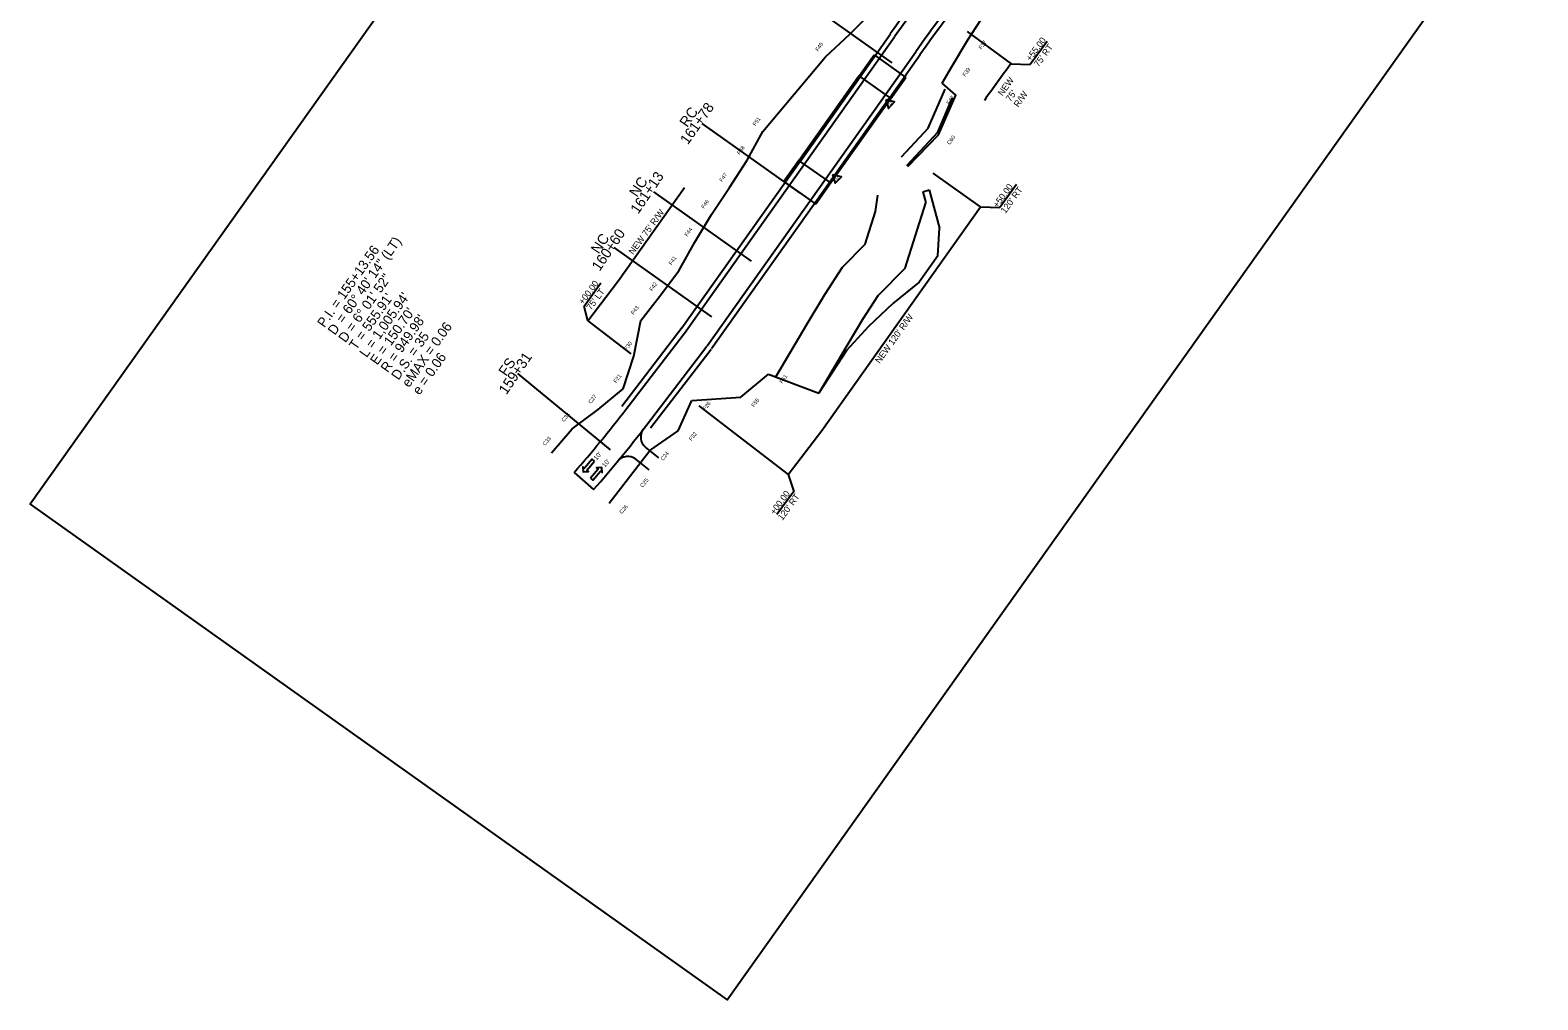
# Model space of a CAD drawing. Extents: x 1775013 to 1776177, y 1129170 to 1130432.
# Drawn here: x 1775013 to 1776177, y 1129170 to 1129918 of the extents above; entities that cross this region are included whole.
import ezdxf

# ---------------------------------------------------------------- set-up
doc = ezdxf.new("R2010")
doc.units = 0
for name, color, linetype in [('RD_EX_SU_Misc', 7, 'Continuous'), ('RD_HC_Data', 7, 'Continuous'), ('RD_HY_Misc', 7, 'Continuous'), ('RD_PD_Bridge', 7, 'Continuous'), ('RD_PD_CstnLmt', 7, 'Continuous'), ('RD_PD_CstnLmt_TX', 7, 'Continuous'), ('RD_PD_Final_TrvlWay', 7, 'Continuous'), ('RD_PD_Final_TX', 7, 'Continuous'), ('RD_PD_GR', 7, 'Continuous'), ('RD_PD_RW', 7, 'Continuous'), ('RD_PD_RW_TX', 7, 'Continuous'), ('RD_SHT_TX', 7, 'Continuous'), ('RD_Sketch2', 7, 'Continuous'), ('RD_Sketch8', 7, 'Continuous')]:
    doc.layers.add(name, color=color, linetype=linetype)

msp = doc.modelspace()

# ---------------------------------------------------------------- linework, layer by layer
at = {"layer": 'RD_EX_SU_Misc'}
for points in [[(1775673.9, 1129863.9), (1775675.9, 1129857.3), (1775680.7, 1129862.3)], [(1775632.8, 1129806.2), (1775634.8, 1129799.6), (1775639.6, 1129804.6)]]:
    msp.add_lwpolyline(points, close=True, dxfattribs=at)
at = {"layer": 'RD_HY_Misc'}
for p, q in [((1775706.6, 1129842.1), (1775719.7, 1129872.2)), ((1775714, 1129838.9), (1775725.5, 1129865.5)), ((1775706.6, 1129842.1), (1775685.8, 1129819.7)), ((1775714, 1129838.9), (1775689.8, 1129813)), ((1775666, 1129777.7), (1775667.8, 1129790.3)), ((1775688.8, 1129734.1), (1775704.8, 1129784.5)), ((1775702.5, 1129793.1), (1775704.8, 1129784.5)), ((1775658, 1129752.7), (1775666, 1129777.7)), ((1775658, 1129752.7), (1775640.3, 1129734.6)), ((1775640.3, 1129734.6), (1775626.6, 1129713.6)), ((1775688.8, 1129734.1), (1775667.7, 1129712.6)), ((1775626.6, 1129713.6), (1775613.8, 1129692.1)), ((1775667.7, 1129712.6), (1775655.9, 1129694.5)), ((1775613.8, 1129692.1), (1775588.8, 1129650.1)), ((1775656.7, 1129695.7), (1775643.8, 1129674.2)), ((1775643.8, 1129674.2), (1775622.1, 1129637.6))]:
    msp.add_line(p, q, dxfattribs=at)
at = {"layer": 'RD_PD_Bridge'}
for p, q in [((1775595.4, 1129800.8), (1775664.9, 1129898.7)), ((1775664.8, 1129898.7), (1775689.3, 1129881.3)), ((1775607.8, 1129816.5), (1775654.1, 1129881.8)), ((1775622, 1129786.8), (1775689.2, 1129881.4)), ((1775677.7, 1129865), (1775689.3, 1129881.3)), ((1775630.5, 1129800.4), (1775676.8, 1129865.7)), ((1775606.9, 1129817.2), (1775595.3, 1129800.9)), ((1775595.3, 1129800.9), (1775619.8, 1129783.5)), ((1775631.4, 1129799.8), (1775619.8, 1129783.5))]:
    msp.add_line(p, q, dxfattribs=at)
msp.add_lwpolyline([(1775606.9, 1129817.2), (1775653.2, 1129882.4), (1775677.7, 1129865), (1775631.4, 1129799.8)], close=True, dxfattribs=at)
at = {"layer": 'RD_PD_CstnLmt'}
for p, q in [((1775646.1, 1129914.5), (1775664, 1129932.5)), ((1775737.2, 1129910.3), (1775750.6, 1129930.9)), ((1775627.4, 1129897.1), (1775646.1, 1129914.5)), ((1775724.6, 1129889.2), (1775737.2, 1129910.3)), ((1775579, 1129839.4), (1775627.4, 1129897.1)), ((1775717.4, 1129876.7), (1775724.6, 1129889.2)), ((1775566.9, 1129817.4), (1775579, 1129839.4)), ((1775714.6, 1129836.9), (1775690.6, 1129812.2)), ((1775553.3, 1129796.3), (1775566.9, 1129817.4)), ((1775539.3, 1129775.6), (1775553.3, 1129796.3)), ((1775702.5, 1129793.1), (1775707.3, 1129794.4)), ((1775707.3, 1129794.4), (1775715.3, 1129765)), ((1775526.4, 1129754.1), (1775539.3, 1129775.6)), ((1775714.1, 1129743.5), (1775715.3, 1129765)), ((1775514.2, 1129732.1), (1775526.4, 1129754.1)), ((1775714.1, 1129743.5), (1775699.6, 1129723.2)), ((1775499.3, 1129712.1), (1775514.2, 1129732.1)), ((1775699.6, 1129723.2), (1775679.4, 1129706.8)), ((1775484.7, 1129693.7), (1775499.3, 1129712.1)), ((1775660.9, 1129689.3), (1775679.4, 1129706.8)), ((1775479.5, 1129666.1), (1775484.7, 1129693.7)), ((1775643.9, 1129670.7), (1775660.9, 1129689.3)), ((1775622.1, 1129637.6), (1775643.9, 1129670.7)), ((1775471.3, 1129640.9), (1775479.5, 1129666.1)), ((1775561.9, 1129634.5), (1775583.4, 1129652.4)), ((1775583.4, 1129652.4), (1775622.1, 1129637.6)), ((1775451.8, 1129624.9), (1775471.3, 1129640.9)), ((1775524.2, 1129631.9), (1775561.9, 1129634.5)), ((1775431.7, 1129610), (1775451.8, 1129624.9)), ((1775513.7, 1129608.5), (1775524.2, 1129631.9)), ((1775416, 1129591.6), (1775431.7, 1129610)), ((1775491.8, 1129593.3), (1775513.7, 1129608.5)), ((1775476.2, 1129573), (1775491.8, 1129593.3)), ((1775460.3, 1129552.8), (1775476.2, 1129573))]:
    msp.add_line(p, q, dxfattribs=at)
msp.add_lwpolyline([(1775714.6, 1129836.9), (1775727.9, 1129867.5), (1775717.4, 1129876.7)], dxfattribs=at)
at = {"layer": 'RD_PD_Final_TrvlWay'}
for p, q in [((1775519.7, 1129685.7), (1775680.7, 1129912.5)), ((1775536.1, 1129674.2), (1775697, 1129900.9)), ((1775473.2, 1129625.1), (1775520, 1129686)), ((1775489.1, 1129612.9), (1775535.8, 1129673.9)), ((1775491.2, 1129578.5), (1775480.9, 1129586.6)), ((1775498.7, 1129587.8), (1775488.5, 1129595.9)), ((1775433.3, 1129576.5), (1775448.3, 1129563.3))]:
    msp.add_line(p, q, dxfattribs=at)
for centre, radius, start, end in [((1777187.3, 1128843), 1847.7, 140.5283, 144.6285), ((1777187.3, 1128843), 1827.7, 140.5283, 144.6285), ((1774727.2, 1130196.9), 940, 318.6957, 322.5307), ((1774727.2, 1130196.9), 960, 318.6957, 322.5307), ((1775494.7, 1129603.8), 10, 142.302, 231.7113), ((1775474.7, 1129578.8), 10, 51.7113, 140.4117)]:
    msp.add_arc(centre, radius, start, end, dxfattribs=at)
at = {"layer": 'RD_PD_Final_TX'}
for points in [[(1775449.1, 1129585.2), (1775447.3, 1129586.8), (1775441.3, 1129579.8), (1775440.1, 1129580.9), (1775440.4, 1129576.9), (1775444.4, 1129577.2), (1775443.1, 1129578.3)], [(1775445.9, 1129572.1), (1775447.7, 1129570.6), (1775453.8, 1129577.5), (1775455, 1129576.4), (1775454.7, 1129580.4), (1775450.7, 1129580.1), (1775451.9, 1129579.1)]]:
    msp.add_lwpolyline(points, close=True, dxfattribs=at)
at = {"layer": 'RD_PD_GR'}
for p, q in [((1775654, 1129881.8), (1775677.5, 1129914.8)), ((1775700.3, 1129898.6), (1775676.9, 1129865.6)), ((1775516.5, 1129688.1), (1775607.7, 1129816.6)), ((1775630.6, 1129800.4), (1775539.3, 1129671.9)), ((1775470.1, 1129627.5), (1775516.8, 1129688.5)), ((1775539, 1129671.4), (1775492.3, 1129610.5))]:
    msp.add_line(p, q, dxfattribs=at)
for radius, start in [(1823.7, 140.5283), (1851.7, 142.0872)]:
    msp.add_arc((1777187.3, 1128843), radius, start, 144.6285, dxfattribs=at)
at = {"layer": 'RD_PD_RW'}
for p, q in [((1775736.8, 1129916.7), (1775770.6, 1129891.7)), ((1775747.1, 1129781.4), (1775710.4, 1129807.5)), ((1775467.5, 1129724.5), (1775518.6, 1129796.4)), ((1775624.5, 1129608.7), (1775747.1, 1129781.4)), ((1775443.8, 1129693.5), (1775467.5, 1129724.5)), ((1775443.8, 1129693.5), (1775477.1, 1129668)), ((1775529.5, 1129627.8), (1775598.6, 1129574.9)), ((1775598.6, 1129574.9), (1775624.5, 1129608.7))]:
    msp.add_line(p, q, dxfattribs=at)
msp.add_arc((1777187.3, 1128843), 1762.7, 143.4903, 144.6285, dxfattribs=at)
at = {"layer": 'RD_PD_RW_TX'}
for p, q in [((1775798.4, 1129908.9), (1775785.4, 1129891.1)), ((1775770.6, 1129891.7), (1775785.4, 1129891.1)), ((1775774.9, 1129798.6), (1775761.9, 1129780.8)), ((1775747.1, 1129781.4), (1775761.9, 1129780.8)), ((1775453.9, 1129722.4), (1775441, 1129704.6)), ((1775443.8, 1129693.5), (1775441, 1129704.6)), ((1775598.6, 1129574.9), (1775602.8, 1129561.8)), ((1775602.8, 1129561.8), (1775589.8, 1129544))]:
    msp.add_line(p, q, dxfattribs=at)
at = {"layer": 'RD_Sketch2'}
msp.add_lwpolyline([(1775639.3, 1130432.2), (1775013.5, 1129552), (1775551.4, 1129169.5), (1776177.2, 1130049.7)], close=True, dxfattribs=at)
at = {"layer": 'RD_Sketch8'}
for p, q in [((1775678.8, 1129892.5), (1775604.2, 1129945.5)), ((1775607.6, 1129792.2), (1775532.2, 1129845.7)), ((1775570.2, 1129739.6), (1775494.9, 1129793.1)), ((1775539.7, 1129696.5), (1775464.3, 1129750)), ((1775461.3, 1129594), (1775389.9, 1129652.7))]:
    msp.add_line(p, q, dxfattribs=at)

# ---------------------------------------------------------------- texts
at = {"layer": 'RD_EX_SU_Misc'}
for p in [(1775677.2, 1129859.8), (1775636.1, 1129802.1)]:
    msp.add_text('U', height=2.4, rotation=46.5431, dxfattribs=at).set_placement(p)
at = {"layer": 'RD_HC_Data'}
for s, p in [('P.I. = 155+13.56', (1775240.6, 1129687.7)), ('    = 60%%d 40\' 14" (LT)', (1775248.7, 1129681.9)), ('D = 6%%d 01\' 52"', (1775256.9, 1129676.1)), ("T = 555.91'", (1775265.1, 1129670.4)), ("L = 1,005.94'", (1775273.2, 1129664.6)), ("E = 150.70'", (1775281.4, 1129658.8)), ("R = 949.98'", (1775289.5, 1129653)), ('eMAX = 0.06', (1775305.9, 1129641.5)), ('D', (1775248.7, 1129681.9)), ('D.S. = 35', (1775297.7, 1129647.2)), ('e = 0.06', (1775314, 1129635.7))]:
    msp.add_text(s, height=7.5, rotation=54.6988, dxfattribs=at).set_placement(p)
at = {"layer": 'RD_PD_CstnLmt_TX'}
for s, rotation, p in [('F45', 54.6285, (1775621.7, 1129901.1)), ('F37', 53.6462, (1775747.7, 1129902.6)), ('F39', 54.4256, (1775735.2, 1129881.6)), ('F42', 54.6285, (1775722.8, 1129860)), ('F51', 54.6285, (1775573.3, 1129843.5)), ('C60', 54.6285, (1775723.3, 1129829)), ('F48', 54.6285, (1775561.1, 1129821.4)), ('F47', 54.6285, (1775547.6, 1129800.4)), ('F46', 54.6285, (1775533.6, 1129779.7)), ('F44', 54.6285, (1775520.7, 1129758.2)), ('F41', 54.6285, (1775508.5, 1129736.2)), ('F42', 54.6285, (1775493.6, 1129716.1)), ('F43', 52.5307, (1775479.2, 1129697.9)), ('F30', 52.5307, (1775474, 1129670.4)), ('F21', 52.5307, (1775465.8, 1129645.2)), ('F61', 54.6285, (1775594, 1129644.8)), ('C27', 51.7113, (1775446.3, 1129629.2)), ('F55', 52.5307, (1775572.2, 1129626.6)), ('C33', 50.2035, (1775425.5, 1129615.2)), ('F26', 52.5307, (1775534.6, 1129624)), ('C33', 48.6957, (1775410.8, 1129596.8)), ('F32', 52.5307, (1775524, 1129600.6)), ('C24', 51.7113, (1775502, 1129585.2)), ('C25', 50.2035, (1775486.2, 1129564.6)), ('C26', 48.6957, (1775470.1, 1129544.2))]:
    msp.add_text(s, height=3, rotation=rotation, dxfattribs=at).set_placement(p)
at = {"layer": 'RD_PD_RW_TX'}
for s, rotation, p in [('+55.00', 53.7139, (1775785.7, 1129893.3)), ("75' RT", 53.7139, (1775791.8, 1129888.9)), ('NEW', 54.3216, (1775764, 1129866.5)), ("75'", 54.3216, (1775770.1, 1129862.1)), ('R/W', 54.3216, (1775776.2, 1129857.8)), ('+50.00', 53.7139, (1775760.2, 1129780.2)), ("120' RT", 53.7139, (1775766.2, 1129775.8)), ("NEW 75' R/W", 53.7139, (1775479, 1129744.1)), ('+00.00', 53.7139, (1775440.4, 1129705.6)), ("75' LT", 53.7139, (1775446.4, 1129701.2)), ("NEW 120' R/W", 54.2233, (1775669.2, 1129660.1)), ('+00.00', 53.7139, (1775588.1, 1129543.4)), ("120' RT", 53.7139, (1775594.1, 1129539))]:
    msp.add_text(s, height=5, rotation=rotation, dxfattribs=at).set_placement(p)
at = {"layer": 'RD_SHT_TX'}
for p in [(1775450.7, 1129585.5), (1775457.1, 1129580)]:
    msp.add_text("10'", height=3.6, rotation=49.923, dxfattribs=at).set_placement(p)
at = {"layer": 'RD_Sketch8'}
for s, rotation, p in [('RC', 54.9501, (1775520.6, 1129842.2)), ('161+78', 54.9501, (1775521.1, 1129828.8)), ('161+13', 55.9265, (1775482.8, 1129775.3)), ('NC', 55.9265, (1775481.9, 1129788.3)), ('160+60', 55.9265, (1775453, 1129731.2)), ('NC', 55.9265, (1775452.3, 1129744.5)), ('159+31', 55.9265, (1775381.1, 1129635.9)), ('FS', 55.9265, (1775381, 1129650.1))]:
    msp.add_text(s, height=8, rotation=rotation, dxfattribs=at).set_placement(p)

doc.saveas('drawing.dxf')
